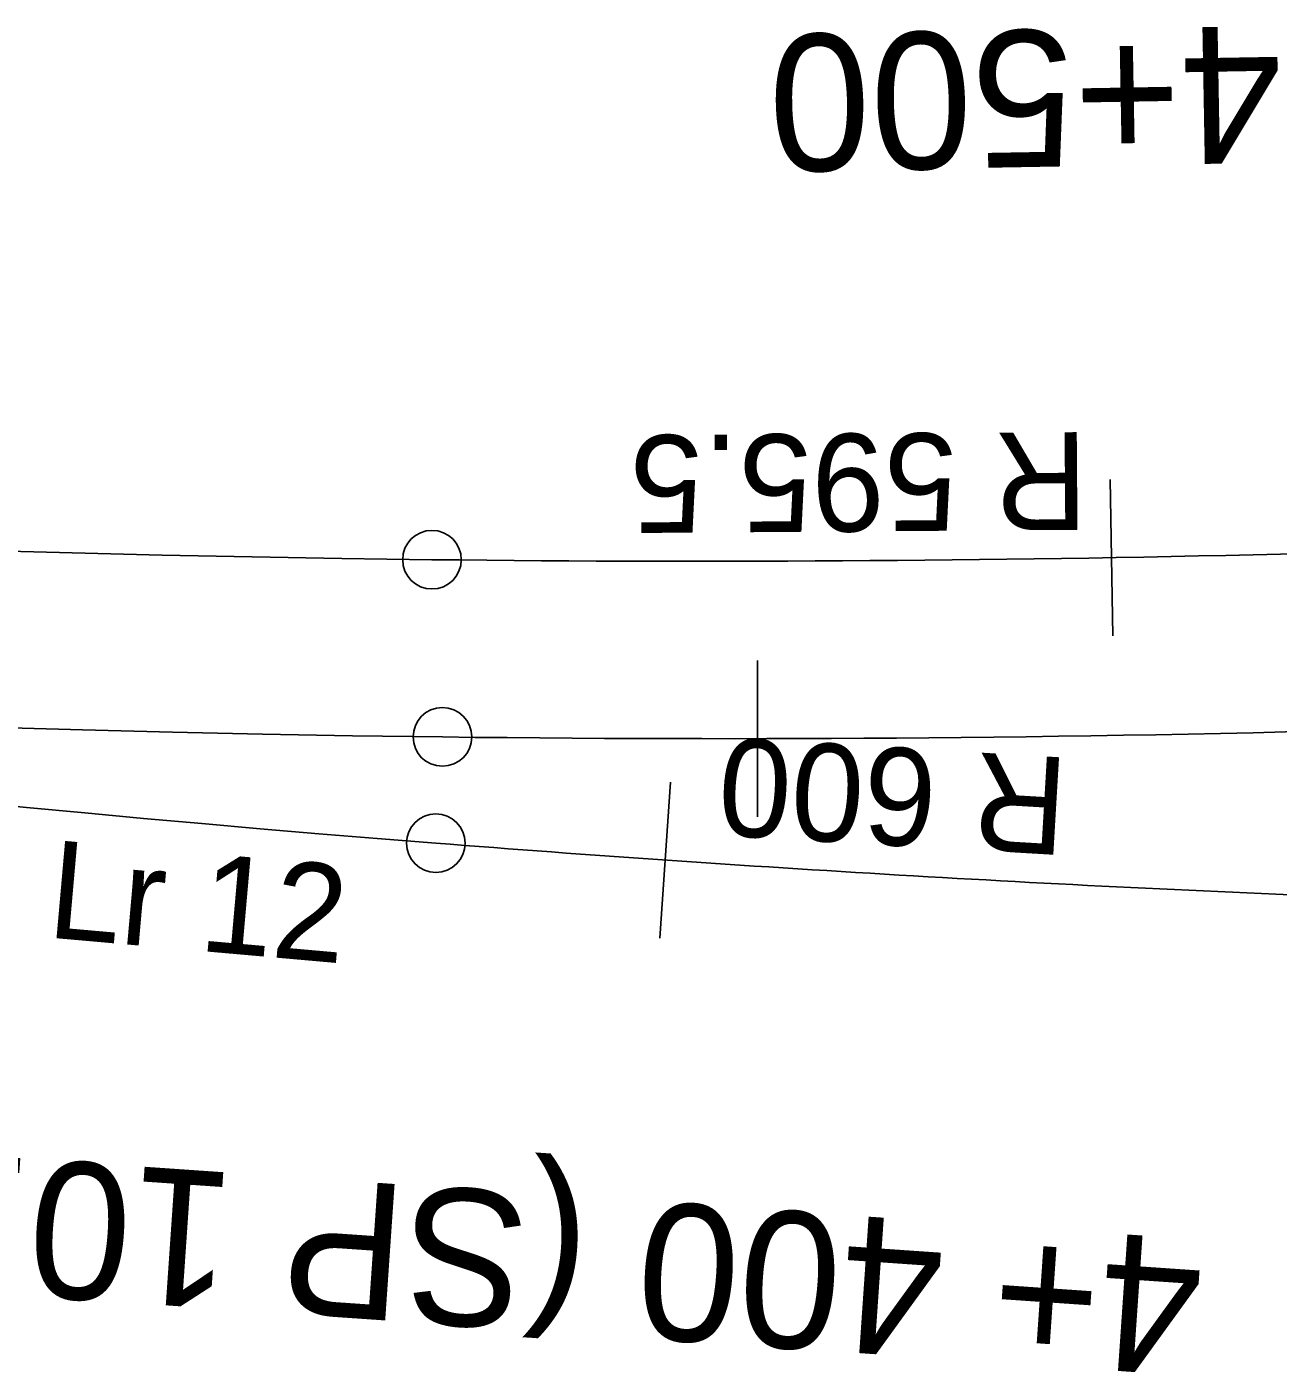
# Model space of a CAD drawing. Extents: x 149855 to 151460, y 6580726 to 6583068.
# Drawn here: x 150162.59 to 150194.61, y 6582159.24 to 6582193.67 of the extents above; entities that cross this region are included whole.
import ezdxf

# ---------------------------------------------------------------- set-up
doc = ezdxf.new("R2010")
doc.units = 0
for name, color, linetype in [('Hektometer L', 7, 'Continuous'), ('Hektometer T', 7, 'Continuous'), ('Spårgeometri T', 7, 'Continuous'), ('Spårmitt L', 7, 'Continuous'), ('Tp bef behålls P', 7, 'Continuous')]:
    doc.layers.add(name, color=color, linetype=linetype)

msp = doc.modelspace()

# ---------------------------------------------------------------- linework, layer by layer
at = {"layer": 'Hektometer L'}
for points in [[(150190.384, 6582178.085), (150190.314, 6582182.084)], [(150181.293, 6582173.453), (150181.287, 6582177.453)], [(150178.787, 6582170.35), (150179.062, 6582174.34)]]:
    msp.add_lwpolyline(points, dxfattribs=at)
at = {"layer": 'Spårmitt L'}
for points in [[(150172.96, 6582180.032), (150170.657, 6582180.063), (150168.354, 6582180.103), (150166.052, 6582180.151), (150163.749, 6582180.207), (150161.447, 6582180.271)], [(150173.225, 6582175.496), (150170.923, 6582175.528), (150168.62, 6582175.568), (150166.317, 6582175.617), (150164.015, 6582175.674), (150161.228, 6582175.754)], [(150173.059, 6582172.778), (150171.561, 6582172.898), (150170.064, 6582173.021), (150168.566, 6582173.148), (150167.07, 6582173.279), (150165.573, 6582173.413), (150164.077, 6582173.551), (150162.581, 6582173.691), (150161.106, 6582173.835)]]:
    msp.add_lwpolyline(points, dxfattribs=at)
for centre, radius, start, end in [((150180.445, 6582775.452), 600, 269.310621, 279.450936), ((150179.867, 6582775.492), 595.5, 269.335434, 271.49227), ((150220.17, 6582770.926), 600, 265.496606, 267.766144)]:
    msp.add_arc(centre, radius, start, end, dxfattribs=at)
at = {"layer": 'Tp bef behålls P'}
for centre in [(150172.96, 6582180.032), (150173.226, 6582175.496), (150173.059, 6582172.778)]:
    msp.add_circle(centre, 0.75, dxfattribs=at)

# ---------------------------------------------------------------- texts
at = {"layer": 'Hektometer T'}
for s, rotation, p in [('4+500', 181.0086, (150194.689, 6582193.694)), ('4+ 400 (SP 101)', 176.0583, (150192.764, 6582162.626))]:
    msp.add_text(s, height=3.5, rotation=rotation, dxfattribs=at).set_placement(p)
at = {"layer": 'Spårgeometri T'}
for s, rotation, p in [('R 595.5', 180.4139, (150189.735, 6582183.298)), ('R 600', 176.6314, (150189.281, 6582174.961)), ('Lr 12', 354.9529, (150163.078, 6582170.369))]:
    msp.add_text(s, height=2.5, rotation=rotation, dxfattribs=at).set_placement(p)

doc.saveas('drawing.dxf')
